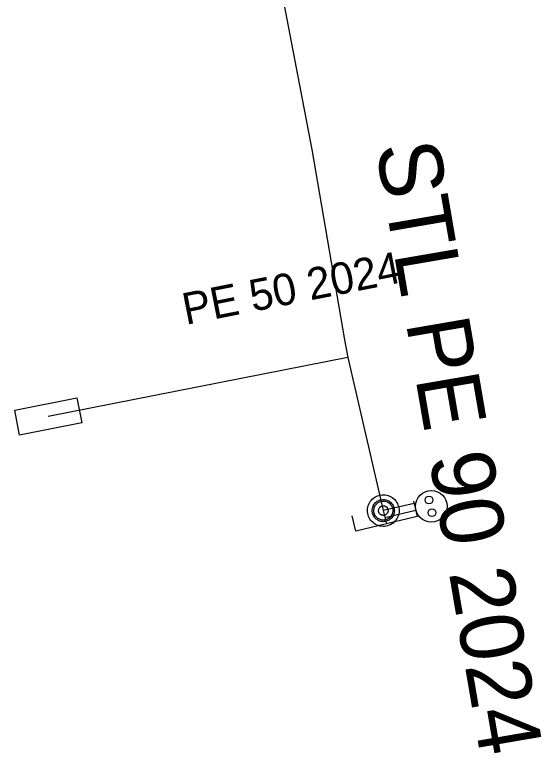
# Model space of a CAD drawing. Extents: x -745298 to -745026, y -1052719 to -1052281.
# Drawn here: x -745280.16 to -745271.83, y -1052455.35 to -1052443.67 of the extents above; entities that cross this region are included whole.
import ezdxf

# ---------------------------------------------------------------- set-up
doc = ezdxf.new("R2010")
doc.units = 0
for name, color, linetype in [('ST Úsek p_ípojky - provoz', 7, 'Continuous'), ('ST Úsek plynovodu - provoz', 7, 'Continuous'), ('Vrstva 1', 7, 'Continuous')]:
    doc.layers.add(name, color=color, linetype=linetype)

msp = doc.modelspace()

# ---------------------------------------------------------------- linework, layer by layer
at = {"layer": 'ST Úsek p_ípojky - provoz'}
msp.add_lwpolyline([(-745274.89, -1052449.09), (-745279.629, -1052450.023)], dxfattribs=at)
at = {"layer": 'ST Úsek plynovodu - provoz'}
msp.add_lwpolyline([(-745276.55, -1052440.11), (-745275.46, -1052445.8), (-745274.942, -1052448.811), (-745274.89, -1052449.09), (-745274.33, -1052451.51), (-745274.28, -1052451.72)], dxfattribs=at)
at = {"layer": 'Vrstva 1'}
for p, q in [((-745273.843, -1052451.397), (-745274.33, -1052451.51)), ((-745274.304, -1052451.618), (-745273.815, -1052451.502))]:
    msp.add_line(p, q, dxfattribs=at)
for points in [[(-745280.081, -1052450.316), (-745280.158, -1052449.923), (-745279.177, -1052449.73), (-745279.1, -1052450.123)], [(-745274.089, -1052451.442), (-745274.084, -1052451.465), (-745274.081, -1052451.49), (-745274.08, -1052451.515), (-745274.082, -1052451.539), (-745274.086, -1052451.563), (-745274.092, -1052451.586), (-745274.101, -1052451.61), (-745274.112, -1052451.632), (-745274.125, -1052451.652), (-745274.14, -1052451.672), (-745274.156, -1052451.689), (-745274.175, -1052451.706), (-745274.195, -1052451.72), (-745274.216, -1052451.733), (-745274.238, -1052451.742), (-745274.262, -1052451.751), (-745274.286, -1052451.756), (-745274.31, -1052451.759), (-745274.335, -1052451.76), (-745274.36, -1052451.758), (-745274.383, -1052451.754), (-745274.407, -1052451.748), (-745274.43, -1052451.739), (-745274.452, -1052451.728), (-745274.473, -1052451.716), (-745274.492, -1052451.7), (-745274.511, -1052451.683), (-745274.526, -1052451.665), (-745274.541, -1052451.645), (-745274.553, -1052451.624), (-745274.563, -1052451.602), (-745274.571, -1052451.578), (-745274.576, -1052451.555), (-745274.58, -1052451.53), (-745274.58, -1052451.505), (-745274.579, -1052451.481), (-745274.574, -1052451.457), (-745274.569, -1052451.433), (-745274.559, -1052451.41), (-745274.549, -1052451.388), (-745274.536, -1052451.367), (-745274.52, -1052451.348), (-745274.504, -1052451.33), (-745274.485, -1052451.314), (-745274.466, -1052451.299), (-745274.444, -1052451.287), (-745274.422, -1052451.277), (-745274.399, -1052451.269), (-745274.375, -1052451.264), (-745274.35, -1052451.26), (-745274.325, -1052451.26), (-745274.301, -1052451.261), (-745274.277, -1052451.266), (-745274.253, -1052451.271), (-745274.23, -1052451.281), (-745274.208, -1052451.291), (-745274.188, -1052451.305), (-745274.168, -1052451.32), (-745274.15, -1052451.336), (-745274.134, -1052451.355), (-745274.12, -1052451.375), (-745274.107, -1052451.396), (-745274.098, -1052451.418)], [(-745274.378, -1052451.342), (-745274.362, -1052451.338), (-745274.345, -1052451.335), (-745274.327, -1052451.335), (-745274.31, -1052451.336), (-745274.293, -1052451.338), (-745274.276, -1052451.344), (-745274.26, -1052451.349), (-745274.245, -1052451.357), (-745274.23, -1052451.366), (-745274.216, -1052451.376), (-745274.204, -1052451.388), (-745274.193, -1052451.401), (-745274.183, -1052451.415), (-745274.174, -1052451.43), (-745274.167, -1052451.446), (-745274.162, -1052451.462), (-745274.158, -1052451.478), (-745274.156, -1052451.496), (-745274.155, -1052451.513), (-745274.156, -1052451.53), (-745274.159, -1052451.547), (-745274.164, -1052451.564), (-745274.169, -1052451.58), (-745274.177, -1052451.595), (-745274.187, -1052451.61), (-745274.197, -1052451.624), (-745274.208, -1052451.636), (-745274.221, -1052451.647), (-745274.235, -1052451.657), (-745274.251, -1052451.666), (-745274.267, -1052451.673), (-745274.283, -1052451.679), (-745274.299, -1052451.683), (-745274.316, -1052451.684), (-745274.334, -1052451.685), (-745274.35, -1052451.684), (-745274.367, -1052451.681), (-745274.384, -1052451.676), (-745274.401, -1052451.671), (-745274.416, -1052451.663), (-745274.43, -1052451.653), (-745274.444, -1052451.643), (-745274.457, -1052451.632), (-745274.468, -1052451.619), (-745274.477, -1052451.605), (-745274.486, -1052451.589), (-745274.493, -1052451.574), (-745274.499, -1052451.557), (-745274.503, -1052451.541), (-745274.504, -1052451.524), (-745274.505, -1052451.506), (-745274.504, -1052451.49), (-745274.502, -1052451.473), (-745274.497, -1052451.456), (-745274.491, -1052451.439), (-745274.483, -1052451.424), (-745274.474, -1052451.41), (-745274.464, -1052451.396), (-745274.452, -1052451.384), (-745274.439, -1052451.372), (-745274.425, -1052451.363), (-745274.41, -1052451.354), (-745274.395, -1052451.346)], [(-745274.289, -1052451.655), (-745274.304, -1052451.658), (-745274.318, -1052451.659), (-745274.333, -1052451.661), (-745274.348, -1052451.659), (-745274.362, -1052451.657), (-745274.376, -1052451.653), (-745274.391, -1052451.647), (-745274.403, -1052451.641), (-745274.415, -1052451.633), (-745274.428, -1052451.624), (-745274.438, -1052451.614), (-745274.448, -1052451.603), (-745274.457, -1052451.591), (-745274.464, -1052451.578), (-745274.47, -1052451.565), (-745274.475, -1052451.551), (-745274.478, -1052451.536), (-745274.48, -1052451.522), (-745274.481, -1052451.507), (-745274.48, -1052451.492), (-745274.477, -1052451.478), (-745274.473, -1052451.464), (-745274.468, -1052451.45), (-745274.461, -1052451.437), (-745274.454, -1052451.424), (-745274.445, -1052451.412), (-745274.434, -1052451.402), (-745274.423, -1052451.392), (-745274.412, -1052451.383), (-745274.399, -1052451.376), (-745274.385, -1052451.37), (-745274.372, -1052451.366), (-745274.357, -1052451.362), (-745274.342, -1052451.36), (-745274.328, -1052451.36), (-745274.313, -1052451.36), (-745274.298, -1052451.363), (-745274.284, -1052451.367), (-745274.271, -1052451.372), (-745274.257, -1052451.378), (-745274.245, -1052451.387), (-745274.233, -1052451.395), (-745274.222, -1052451.406), (-745274.212, -1052451.417), (-745274.204, -1052451.429), (-745274.197, -1052451.441), (-745274.191, -1052451.455), (-745274.186, -1052451.468), (-745274.182, -1052451.483), (-745274.181, -1052451.498), (-745274.181, -1052451.512), (-745274.181, -1052451.527), (-745274.183, -1052451.542), (-745274.187, -1052451.556), (-745274.193, -1052451.57), (-745274.199, -1052451.583), (-745274.207, -1052451.595), (-745274.216, -1052451.607), (-745274.226, -1052451.618), (-745274.237, -1052451.628), (-745274.249, -1052451.636), (-745274.262, -1052451.644), (-745274.275, -1052451.649)], [(-745274.31, -1052451.582), (-745274.317, -1052451.584), (-745274.324, -1052451.585), (-745274.331, -1052451.585), (-745274.339, -1052451.584), (-745274.346, -1052451.583), (-745274.354, -1052451.581), (-745274.36, -1052451.579), (-745274.367, -1052451.575), (-745274.373, -1052451.571), (-745274.379, -1052451.568), (-745274.385, -1052451.562), (-745274.389, -1052451.557), (-745274.394, -1052451.55), (-745274.397, -1052451.544), (-745274.401, -1052451.538), (-745274.402, -1052451.531), (-745274.404, -1052451.523), (-745274.406, -1052451.516), (-745274.405, -1052451.509), (-745274.405, -1052451.501), (-745274.403, -1052451.494), (-745274.402, -1052451.487), (-745274.4, -1052451.48), (-745274.396, -1052451.473), (-745274.392, -1052451.467), (-745274.387, -1052451.462), (-745274.383, -1052451.455), (-745274.377, -1052451.451), (-745274.37, -1052451.446), (-745274.364, -1052451.443), (-745274.357, -1052451.44), (-745274.351, -1052451.438), (-745274.344, -1052451.436), (-745274.336, -1052451.435), (-745274.329, -1052451.435), (-745274.322, -1052451.435), (-745274.314, -1052451.437), (-745274.308, -1052451.438), (-745274.3, -1052451.441), (-745274.294, -1052451.444), (-745274.288, -1052451.448), (-745274.282, -1052451.453), (-745274.276, -1052451.458), (-745274.271, -1052451.463), (-745274.267, -1052451.469), (-745274.263, -1052451.476), (-745274.26, -1052451.483), (-745274.258, -1052451.489), (-745274.256, -1052451.497), (-745274.255, -1052451.504), (-745274.255, -1052451.511), (-745274.255, -1052451.518), (-745274.257, -1052451.526), (-745274.259, -1052451.533), (-745274.261, -1052451.54), (-745274.265, -1052451.546), (-745274.269, -1052451.552), (-745274.273, -1052451.558), (-745274.279, -1052451.564), (-745274.283, -1052451.569), (-745274.29, -1052451.573), (-745274.296, -1052451.577), (-745274.303, -1052451.58)]]:
    msp.add_lwpolyline(points, close=True, dxfattribs=at)
msp.add_lwpolyline([(-745273.851, -1052451.361), (-745273.794, -1052451.604), (-745274.766, -1052451.836), (-745274.824, -1052451.593)], dxfattribs=at)
for centre, radius in [((-745273.571, -1052451.442), 0.249), ((-745273.609, -1052451.342), 0.0614), ((-745273.561, -1052451.543), 0.0614)]:
    msp.add_circle(centre, radius, dxfattribs=at)

# ---------------------------------------------------------------- texts
at = {"layer": 'ST Úsek p_ípojky - provoz'}
msp.add_text('PE 50 2024', height=0.5, rotation=11.1378, dxfattribs=at).set_placement((-745277.453, -1052448.575))
at = {"layer": 'ST Úsek plynovodu - provoz'}
msp.add_text('STL PE 90 2024', height=1, rotation=279.7614, dxfattribs=at).set_placement((-745274.454, -1052445.751))

doc.saveas('drawing.dxf')
